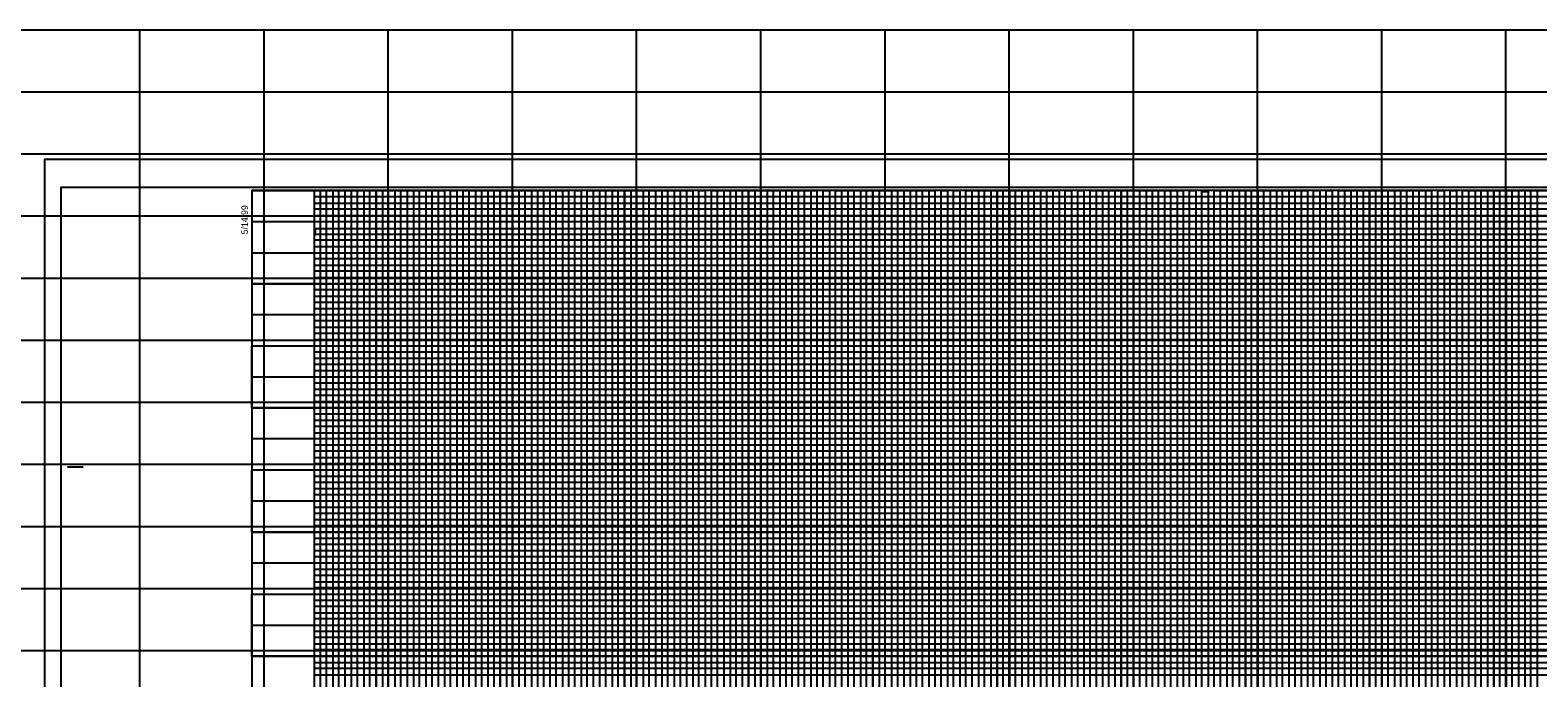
# Model space of a CAD drawing. Extents: x 553912 to 567693, y 512355 to 537539.
# Drawn here: x 559761 to 560975, y 521733 to 522255 of the extents above; entities that cross this region are included whole.
import ezdxf

# ---------------------------------------------------------------- set-up
doc = ezdxf.new("R2010")
doc.units = 0
for name, color, linetype in [('Default', 7, 'Continuous'), ('Old_Level_42', 7, 'Continuous'), ('Old_Level_51', 7, 'Continuous'), ('Old_Level_53', 7, 'Continuous'), ('Old_Level_54', 7, 'Continuous'), ('Prop ROW Permanent Easement CELL', 7, 'Continuous'), ('Sheet Profile Grid Major CELL', 7, 'Continuous'), ('Sheet Row Area Data CELL', 7, 'Continuous'), ('Sheet Summary Guardrail CELL', 7, 'Continuous')]:
    doc.layers.add(name, color=color, linetype=linetype)

msp = doc.modelspace()

# ---------------------------------------------------------------- linework, layer by layer
at = {"layer": 'Default'}
msp.add_lwpolyline([(561456.7, 522150.4), (559772.7, 522150.4), (559772.7, 521050.4), (561456.7, 521050.4)], close=True, dxfattribs=at)
at = {"layer": 'Old_Level_42'}
for p, q in [((559989.7, 522125.4), (559989.7, 521100.4)), ((560039.7, 522125.4), (560039.7, 521100.4)), ((560089.7, 522125.4), (560089.7, 521100.4)), ((560139.7, 522125.4), (560139.7, 521100.4)), ((560189.7, 522125.4), (560189.7, 521100.4)), ((560239.7, 522125.4), (560239.7, 521100.4)), ((560289.7, 522125.4), (560289.7, 521100.4)), ((560339.7, 522125.4), (560339.7, 521100.4)), ((560389.7, 522125.4), (560389.7, 521100.4)), ((560439.7, 522125.4), (560439.7, 521100.4)), ((560489.7, 522125.4), (560489.7, 521100.4)), ((560539.7, 522125.4), (560539.7, 521100.4)), ((560589.7, 522125.4), (560589.7, 521100.4)), ((560639.7, 522125.4), (560639.7, 521100.4)), ((560689.7, 522125.4), (560689.7, 521100.4)), ((560739.7, 522125.4), (560739.7, 521100.4)), ((560789.7, 522125.4), (560789.7, 521100.4)), ((560839.7, 522125.4), (560839.7, 521100.4)), ((560889.7, 522125.4), (560889.7, 521100.4)), ((560939.7, 522125.4), (560939.7, 521100.4)), ((559939.7, 522100.4), (561239.6, 522100.4)), ((559939.7, 522050.4), (561239.6, 522050.4)), ((559939.7, 522000.4), (561239.6, 522000.4)), ((559939.7, 521950.4), (561439.7, 521950.4)), ((559939.7, 521900.4), (561439.7, 521900.4)), ((559939.7, 521850.4), (561439.7, 521850.4)), ((559939.7, 521800.4), (561439.7, 521800.4)), ((559939.7, 521750.4), (561439.7, 521750.4))]:
    msp.add_line(p, q, dxfattribs=at)
at = {"layer": 'Old_Level_51'}
msp.add_lwpolyline([(561452.2, 522128), (559785.7, 522128), (559785.7, 521072.9), (561452.2, 521072.9)], close=True, dxfattribs=at)
at = {"layer": 'Old_Level_53'}
msp.add_line((559791.2, 521902.9), (559803.7, 521902.9), dxfattribs=at)
msp.add_lwpolyline([(561439.7, 522125.4), (559939.7, 522125.4), (559939.7, 521075.4), (561439.7, 521075.4)], close=True, dxfattribs=at)
at = {"layer": 'Old_Level_54'}
for points in [[(559939.7, 522125.4), (559989.7, 522125.4), (559989.7, 521100.4)], [(560039.7, 521100.4), (560039.7, 522125.4), (560089.7, 522125.4), (560089.7, 521100.4)], [(560139.7, 521100.4), (560139.7, 522125.4), (560189.7, 522125.4), (560189.7, 521100.4)], [(560239.7, 521100.4), (560239.7, 522125.4), (560289.7, 522125.4), (560289.7, 521100.4)], [(560339.7, 521100.4), (560339.7, 522125.4), (560389.7, 522125.4), (560389.7, 521100.4)], [(560439.7, 521100.4), (560439.7, 522125.4), (560489.7, 522125.4), (560489.7, 521100.4)], [(560539.7, 521100.4), (560539.7, 522125.4), (560589.7, 522125.4), (560589.7, 521100.4)], [(560639.7, 521100.4), (560639.7, 522125.4), (560689.7, 522125.4), (560689.7, 521100.4)], [(560739.7, 521100.4), (560739.7, 522125.4), (560789.7, 522125.4), (560789.7, 521100.4)], [(560839.7, 521100.4), (560839.7, 522125.4), (560889.7, 522125.4), (560889.7, 521100.4)], [(560939.7, 521100.4), (560939.7, 522125.4), (560989.7, 522125.4)], [(561239.6, 522050.4), (559939.8, 522050.4), (559939.8, 522100.4), (561239.6, 522100.4)], [(561439.7, 521950.4), (559939.7, 521950.4), (559939.7, 522000.4), (561239.6, 522000.4)], [(561439.7, 521850.4), (559939.7, 521850.4), (559939.7, 521900.4), (561439.7, 521900.4)], [(561439.7, 521750.4), (559939.7, 521750.4), (559939.7, 521800.4), (561439.7, 521800.4)]]:
    msp.add_lwpolyline(points, dxfattribs=at)
at = {"layer": 'Prop ROW Permanent Easement CELL'}
for points in [[(560014.7, 521100.4), (560014.7, 522125.4), (560064.7, 522125.4), (560064.7, 521100.4)], [(560114.7, 521100.4), (560114.7, 522125.4), (560164.7, 522125.4), (560164.7, 521100.4)], [(560214.7, 521100.4), (560214.7, 522125.4), (560264.7, 522125.4), (560264.7, 521100.4)], [(560314.7, 521100.4), (560314.7, 522125.4), (560364.7, 522125.4), (560364.7, 521100.4)], [(560414.7, 521100.4), (560414.7, 522125.4), (560464.7, 522125.4), (560464.7, 521100.4)], [(560514.7, 521100.4), (560514.7, 522125.4), (560564.7, 522125.4), (560564.7, 521100.4)], [(560614.7, 521100.4), (560614.7, 522125.4), (560664.7, 522125.4), (560664.7, 521100.4)], [(560714.7, 521100.4), (560714.7, 522125.4), (560764.7, 522125.4), (560764.7, 521100.4)], [(560814.7, 521100.4), (560814.7, 522125.4), (560864.7, 522125.4), (560864.7, 521100.4)], [(560914.7, 521100.4), (560914.7, 522125.4), (560964.7, 522125.4), (560964.7, 521100.4)], [(559939.7, 522075.4), (561239.6, 522075.4)], [(561239.6, 522025.4), (559939.7, 522025.4), (559939.7, 521975.4), (561239.6, 521975.4)], [(561439.7, 521925.4), (559939.7, 521925.4), (559939.7, 521875.4), (561439.7, 521875.4)], [(561439.7, 521825.4), (559939.7, 521825.4), (559939.7, 521775.4), (561439.7, 521775.4)]]:
    msp.add_lwpolyline(points, dxfattribs=at)
at = {"layer": 'Sheet Profile Grid Major CELL'}
for p, q in [((563849.5, 522254.7), (557249.5, 522254.7)), ((559849.5, 521054.7), (559849.5, 522254.7)), ((559949.5, 521054.7), (559949.5, 522254.7)), ((560049.5, 521054.7), (560049.5, 522254.7)), ((560149.5, 521054.7), (560149.5, 522254.7)), ((560249.5, 521054.7), (560249.5, 522254.7)), ((560349.5, 521054.7), (560349.5, 522254.7)), ((560449.5, 521054.7), (560449.5, 522254.7)), ((560549.5, 521054.7), (560549.5, 522254.7)), ((560649.5, 521054.7), (560649.5, 522254.7)), ((560749.5, 521054.7), (560749.5, 522254.7)), ((560849.5, 521054.7), (560849.5, 522254.7)), ((560949.5, 521054.7), (560949.5, 522254.7)), ((563849.5, 522204.7), (557249.5, 522204.7)), ((563849.5, 522154.7), (557249.5, 522154.7)), ((563849.5, 522104.7), (557249.5, 522104.7)), ((563849.5, 522054.7), (557249.5, 522054.7)), ((563849.5, 522004.7), (557249.5, 522004.7)), ((563849.5, 521954.7), (557249.5, 521954.7)), ((563849.5, 521904.7), (557249.5, 521904.7)), ((563849.5, 521854.7), (557249.5, 521854.7)), ((563849.5, 521804.7), (557249.5, 521804.7)), ((563849.5, 521754.7), (557249.5, 521754.7))]:
    msp.add_line(p, q, dxfattribs=at)
at = {"layer": 'Sheet Row Area Data CELL'}
for p, q in [((561456.7, 522150.4), (559772.7, 522150.4)), ((559772.7, 522150.4), (559772.7, 521050.4))]:
    msp.add_line(p, q, dxfattribs=at)
at = {"layer": 'Sheet Summary Guardrail CELL'}
for p, q in [((561389.7, 521945.4), (559989.7, 521945.4)), ((559989.7, 521945.4), (559989.7, 521940.4)), ((559989.7, 521940.4), (561389.7, 521940.4)), ((561389.7, 521920.4), (559989.7, 521920.4))]:
    msp.add_line(p, q, dxfattribs=at)
for points in [[(559994.7, 522125.4), (559999.7, 522125.4), (560004.7, 522125.4), (560009.7, 522125.4), (560019.7, 522125.4), (559986.6, 522125.4), (559991.6, 522125.4), (559949.7, 522125.4), (559954.7, 522125.4), (559959.7, 522125.4), (559969.7, 522125.4), (559974.7, 522125.4), (559979.7, 522125.4), (559984.7, 522125.4), (559994.7, 522125.4), (559994.7, 521100.4)], [(561239.6, 522120.4), (559989.7, 522120.4), (559989.7, 522115.4), (561239.6, 522115.4)], [(559999.7, 521100.4), (559999.7, 522125.4), (560004.7, 522125.4), (560004.7, 521100.4)], [(560009.7, 521100.4), (560009.7, 522125.4), (560019.7, 522125.4), (560019.7, 521100.4)], [(560024.7, 521100.4), (560024.7, 522125.4), (560029.7, 522125.4), (560029.7, 521100.4)], [(560034.7, 521100.4), (560034.7, 522125.4), (560044.7, 522125.4), (560044.7, 521100.4)], [(560049.7, 521100.4), (560049.7, 522125.4), (560054.7, 522125.4), (560054.7, 521100.4)], [(560059.7, 521100.4), (560059.7, 522125.4), (560069.7, 522125.4), (560069.7, 521100.4)], [(560074.7, 521100.4), (560074.7, 522125.4), (560079.7, 522125.4), (560079.7, 521100.4)], [(560084.7, 521100.4), (560084.7, 522125.4), (560094.7, 522125.4), (560094.7, 521100.4)], [(560099.7, 521100.4), (560099.7, 522125.4), (560104.7, 522125.4), (560104.7, 521100.4)], [(560109.7, 521100.4), (560109.7, 522125.4), (560119.7, 522125.4), (560119.7, 521100.4)], [(560124.7, 521100.4), (560124.7, 522125.4), (560129.7, 522125.4), (560129.7, 521100.4)], [(560134.7, 521100.4), (560134.7, 522125.4), (560144.7, 522125.4), (560144.7, 521100.4)], [(560149.7, 521100.4), (560149.7, 522125.4), (560154.7, 522125.4), (560154.7, 521100.4)], [(560159.7, 521100.4), (560159.7, 522125.4), (560169.7, 522125.4), (560169.7, 521100.4)], [(560174.7, 521100.4), (560174.7, 522125.4), (560179.7, 522125.4), (560179.7, 521100.4)], [(560184.7, 521100.4), (560184.7, 522125.4), (560194.7, 522125.4), (560194.7, 521100.4)], [(560199.7, 521100.4), (560199.7, 522125.4), (560199.7, 522125.4), (560204.7, 522125.4), (560204.7, 521100.4)], [(560209.7, 521100.4), (560209.7, 522125.4), (560219.7, 522125.4), (560219.7, 521100.4)], [(560224.7, 521100.4), (560224.7, 522125.4), (560229.7, 522125.4), (560229.7, 521100.4)], [(560234.7, 521100.4), (560234.7, 522125.4), (560244.7, 522125.4), (560244.7, 521100.4)], [(560249.7, 521100.4), (560249.7, 522125.4), (560254.7, 522125.4), (560254.7, 521100.4)], [(560259.7, 521100.4), (560259.7, 522125.4), (560269.7, 522125.4), (560269.7, 521100.4)], [(560274.7, 521100.4), (560274.7, 522125.4), (560279.7, 522125.4), (560279.7, 521100.4)], [(560284.7, 521100.4), (560284.7, 522125.4), (560294.7, 522125.4), (560294.7, 521100.4)], [(560299.7, 521100.4), (560299.7, 522125.4), (560304.7, 522125.4), (560304.7, 521100.4)], [(560309.7, 521100.4), (560309.7, 522125.4), (560319.7, 522125.4), (560319.7, 521100.4)], [(560324.7, 522125.4), (560324.7, 521100.4), (560329.7, 521100.4), (560329.7, 522125.4)], [(560324.7, 522124.8), (560324.7, 521100.4), (560329.7, 521100.4), (560329.7, 522124.8)], [(560334.7, 521100.4), (560334.7, 522125.4), (560344.7, 522125.4), (560344.7, 521100.4)], [(560349.7, 521100.4), (560349.7, 522125.4), (560354.7, 522125.4), (560354.7, 521100.4)], [(560359.7, 521100.4), (560359.7, 522125.4), (560369.7, 522125.4), (560369.7, 521100.4)], [(560374.7, 521100.4), (560374.7, 522125.4), (560379.7, 522125.4), (560379.7, 521100.4)], [(560384.7, 521100.4), (560384.7, 522125.4), (560394.7, 522125.4), (560394.7, 521100.4)], [(560399.7, 521100.4), (560399.7, 522125.4), (560404.7, 522125.4), (560404.7, 521100.4)], [(560409.7, 521100.4), (560409.7, 522125.4), (560419.7, 522125.4), (560419.7, 521100.4)], [(560424.7, 521100.4), (560424.7, 522125.4), (560429.7, 522125.4), (560429.7, 521100.4)], [(560434.7, 521100.4), (560434.7, 522125.4), (560444.7, 522125.4), (560444.7, 521100.4)], [(560449.7, 521100.4), (560449.7, 522125.4), (560454.7, 522125.4), (560454.7, 521100.4)], [(560459.7, 521100.4), (560459.7, 522125.4), (560469.7, 522125.4), (560469.7, 521100.4)], [(560474.7, 522125.4), (560474.7, 521100.4), (560479.7, 521100.4), (560479.7, 522125.4), (560484.7, 522125.4), (560484.7, 521100.4), (560494.7, 521100.4), (560494.7, 522125.4), (560499.7, 522125.4), (560499.7, 521100.4), (560504.7, 521100.4), (560504.7, 522125.4), (560509.7, 522125.4), (560509.7, 521100.4)], [(560519.7, 521100.4), (560519.7, 522125.4), (560524.7, 522125.4), (560524.7, 521100.4)], [(560529.7, 521100.4), (560529.7, 522125.4), (560534.7, 522125.4), (560534.7, 521100.4)], [(560544.7, 521100.4), (560544.7, 522125.4), (560549.7, 522125.4), (560549.7, 521100.4)], [(560554.7, 521100.4), (560554.7, 522125.4), (560559.7, 522125.4), (560559.7, 521100.4)], [(560569.7, 521100.4), (560569.7, 522125.4), (560574.7, 522125.4), (560574.7, 521100.4)], [(560579.7, 521100.4), (560579.7, 522125.4), (560584.7, 522125.4), (560584.7, 521100.4)], [(560594.7, 521100.4), (560594.7, 522125.4), (560599.7, 522125.4), (560599.7, 521100.4)], [(560604.7, 521100.4), (560604.7, 522125.4), (560609.7, 522125.4), (560609.7, 521100.4)], [(560619.7, 521100.4), (560619.7, 522125.4), (560624.7, 522125.4), (560624.7, 521100.4)], [(560629.7, 521100.4), (560629.7, 522125.4), (560634.7, 522125.4), (560634.7, 521100.4)], [(560644.7, 521100.4), (560644.7, 522125.4), (560649.7, 522125.4), (560649.7, 521100.4)], [(560654.7, 521100.4), (560654.7, 522125.4), (560659.7, 522125.4), (560659.7, 521100.4)], [(560669.7, 521100.4), (560669.7, 522125.4), (560674.7, 522125.4), (560674.7, 521100.4)], [(560679.7, 521100.4), (560679.7, 522125.4), (560684.7, 522125.4), (560684.7, 521100.4)], [(560694.7, 521100.4), (560694.7, 522125.4), (560699.7, 522125.4), (560699.7, 521100.4)], [(560704.7, 521100.4), (560704.7, 522124.8), (560709.7, 522124.8), (560709.7, 521100.4)], [(560719.7, 521100.4), (560719.7, 522125.4), (560724.7, 522125.4), (560724.7, 521100.4)], [(560729.7, 521100.4), (560729.7, 522125.4), (560734.7, 522125.4), (560734.7, 521100.4)], [(560744.7, 521100.4), (560744.7, 522125.4), (560749.7, 522125.4), (560749.7, 521100.4)], [(560754.7, 521100.4), (560754.7, 522125.4), (560759.7, 522125.4), (560759.7, 521100.4)], [(560769.7, 521100.4), (560769.7, 522125.4), (560774.7, 522125.4), (560774.7, 521100.4)], [(560779.7, 521100.4), (560779.7, 522125.4), (560784.7, 522125.4), (560784.7, 521100.4)], [(560794.7, 521100.4), (560794.7, 522125.4), (560799.7, 522125.4), (560799.7, 521100.4)], [(560804.7, 521100.4), (560804.7, 522125.4), (560809.7, 522125.4), (560809.7, 521100.4)], [(560819.7, 521100.4), (560819.7, 522125.4), (560824.7, 522125.4), (560824.7, 521100.4)], [(560829.7, 521100.4), (560829.7, 522125.4), (560834.7, 522125.4), (560834.7, 521100.4)], [(560844.7, 521100.4), (560844.7, 522125.4), (560849.7, 522125.4), (560849.7, 521100.4)], [(560854.7, 521100.4), (560854.7, 522125.4), (560859.7, 522125.4), (560859.7, 521100.4)], [(560869.7, 521100.4), (560869.7, 522125.4), (560874.7, 522125.4), (560874.7, 521100.4)], [(560879.7, 521100.4), (560879.7, 522125.4), (560884.7, 522125.4), (560884.7, 521100.4)], [(560894.7, 521100.4), (560894.7, 522125.4), (560899.7, 522125.4), (560899.7, 521100.4)], [(560904.7, 521100.4), (560904.7, 522125.4), (560909.7, 522125.4), (560909.7, 521100.4)], [(560919.7, 521100.4), (560919.7, 522125.4), (560924.7, 522125.4), (560924.7, 521100.4)], [(560929.7, 521100.4), (560929.7, 522125.4), (560934.7, 522125.4), (560934.7, 521100.4)], [(560944.7, 521100.4), (560944.7, 522125.4), (560949.7, 522125.4), (560949.7, 521100.4)], [(560954.7, 521100.4), (560954.7, 522125.4), (560959.7, 522125.4), (560959.7, 521100.4)], [(560969.7, 521100.4), (560969.7, 522125.4), (560974.7, 522125.4), (560974.7, 521100.4)], [(561239.6, 522110.4), (559989.7, 522110.4), (559989.7, 522105.4), (561239.6, 522105.4)], [(561239.6, 522085.4), (559989.7, 522085.4), (559989.7, 522080.4), (561239.6, 522080.4)], [(561239.6, 522094.7), (559990.7, 522094.7), (559990.7, 522090.4), (561239.6, 522090.4)], [(561239.6, 522070.4), (559989.7, 522070.4), (559989.7, 522065.4), (561239.6, 522065.4)], [(561239.6, 522060.4), (559989.7, 522060.4), (559989.7, 522055.4), (561239.6, 522055.4)], [(561239.6, 522045.4), (559989.7, 522045.4), (559989.7, 522040.4), (561239.6, 522040.4)], [(561239.6, 522035.4), (559989.7, 522035.4), (559989.7, 522030.4), (561239.6, 522030.4)], [(561239.6, 522020.4), (559989.7, 522020.4), (559989.7, 522015.4), (561239.6, 522015.4)], [(561239.6, 522010.4), (559989.7, 522010.4), (559989.7, 522005.4), (561239.6, 522005.4)], [(561239.6, 521995.4), (559989.7, 521995.4), (559989.7, 521990.4), (561239.6, 521990.4)], [(561239.6, 521985.4), (559989.7, 521985.4), (559989.7, 521985.4), (559989.7, 521965.4), (561239.6, 521965.4)], [(559989.7, 521980.4), (561239.6, 521980.4)], [(561239.6, 521970.4), (559989.7, 521970.4)], [(561389.7, 521960.4), (559989.7, 521960.4), (559989.7, 521955.4), (561389.7, 521955.4)], [(561389.7, 521935.4), (559989.7, 521935.4), (559989.7, 521930.4), (561389.7, 521930.4)], [(561389.7, 521915.4), (559989.7, 521915.4), (559989.7, 521910.4), (561389.7, 521910.4)], [(561389.7, 521905.4), (559989.7, 521905.4)], [(559989.7, 521895.4), (561389.7, 521895.4)], [(561389.7, 521890.4), (559989.7, 521890.4), (559989.7, 521885.4), (561389.7, 521885.4)], [(561389.7, 521880.4), (559989.7, 521880.4), (559989.7, 521870.4), (561389.7, 521870.4)], [(561389.7, 521865.4), (559989.7, 521865.4), (559989.7, 521860.4), (561389.7, 521860.4)], [(561389.7, 521855.4), (559989.7, 521855.4), (559989.7, 521845.4), (561389.7, 521845.4)], [(561389.7, 521840.4), (559989.7, 521840.4), (559989.7, 521835.4), (561389.7, 521835.4)], [(561389.7, 521830.4), (559989.7, 521830.4), (559989.7, 521820.4), (561389.7, 521820.4)], [(561389.7, 521815.4), (559989.7, 521815.4), (559989.7, 521810.4), (561389.7, 521810.4)], [(561389.7, 521805.4), (559989.7, 521805.4), (559989.7, 521795.4), (561389.7, 521795.4)], [(561389.7, 521790.4), (559989.7, 521790.4), (559989.7, 521785.4), (561389.7, 521785.4)], [(561389.7, 521780.4), (559989.7, 521780.4), (559989.7, 521770.4), (561389.7, 521770.4)], [(561389.7, 521765.4), (559989.7, 521765.4), (559989.7, 521760.4), (561389.7, 521760.4)], [(561389.7, 521755.4), (559989.7, 521755.4), (559989.7, 521745.4), (561389.7, 521745.4)], [(561389.7, 521740.4), (559989.7, 521740.4), (559989.7, 521735.4), (561389.7, 521735.4)]]:
    msp.add_lwpolyline(points, dxfattribs=at)

# ---------------------------------------------------------------- texts
at = {"layer": 'Old_Level_53'}
msp.add_text('5/14/99', height=5.25, rotation=90, dxfattribs=at).set_placement((559936.4, 522090.2))

doc.saveas('drawing.dxf')
